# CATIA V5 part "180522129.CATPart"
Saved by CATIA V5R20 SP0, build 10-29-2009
Part number: 花瓶
Material "Fabric 4": density 200 kg/m3
Bounding box of the stored display mesh (mm): x -49.943 to 63.84, y -49.943 to 49.892, z 0 to 154
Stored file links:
  D:\工图\180522129.CATPart
  C:\Program Files\Dassault Systemes\B20\win_b64\startup\materials\Catalog.CATMaterial
  C:\Program Files\Dassault Systemes\B20\win_b64\startup\materials\canvas.png
  C:\Program Files\Dassault Systemes\B20\win_b64\startup\materials\solar_panel.jpg
  C:\Program Files\Dassault Systemes\B20\win_b64\startup\materials\summer_sky.jpg
  C:\Program Files\Dassault Systemes\B20\win_b64\startup\materials\green_env_512x512.jpg
  C:\Program Files\Dassault Systemes\B20\win_b64\startup\materials\losange_fabric.jpg
  C:\Program Files\Dassault Systemes\B20\win_b64\startup\materials\blue_fabric_01.jpg
  C:\Program Files\Dassault Systemes\B20\win_b64\startup\materials\office_carpet.jpg
  C:\Program Files\Dassault Systemes\B20\win_b64\startup\materials\wallpaper_01.jpg
  C:\Program Files\Dassault Systemes\B20\win_b64\startup\materials\grey_carpet.jpg
  C:\Program Files\Dassault Systemes\B20\win_b64\startup\materials\raw_polystyren.jpg
  C:\Program Files\Dassault Systemes\B20\win_b64\startup\materials\sunset.jpg
  C:\Program Files\Dassault Systemes\B20\win_b64\startup\materials\blue_carpet.jpg
  C:\Program Files\Dassault Systemes\B20\win_b64\startup\materials\wallpaper_03.jpg
  C:\Program Files\Dassault Systemes\B20\win_b64\startup\materials\wallpaper_02.jpg
  C:\Program Files\Dassault Systemes\B20\win_b64\startup\materials\DS_star.jpg
  C:\Program Files\Dassault Systemes\B20\win_b64\startup\materials\strip_wall.jpg
  C:\Program Files\Dassault Systemes\B20\win_b64\startup\materials\malachite.jpg
  C:\Program Files\Dassault Systemes\B20\win_b64\startup\materials\pink_marble.jpg
  C:\Program Files\Dassault Systemes\B20\win_b64\startup\materials\blue_env_512x512.jpg
  C:\Program Files\Dassault Systemes\B20\win_b64\startup\materials\red_env_512x512.jpg
  C:\Program Files\Dassault Systemes\B20\win_b64\startup\materials\kingwood.jpg
  C:\Program Files\Dassault Systemes\B20\win_b64\startup\materials\brushed_metal2.jpg
  C:\Program Files\Dassault Systemes\B20\win_b64\startup\materials\blue_fabric_02.jpg
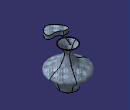
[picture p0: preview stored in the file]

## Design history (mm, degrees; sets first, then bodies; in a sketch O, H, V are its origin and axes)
Body1 (main body), material "Fabric 4"
  Plane1: type Offset, RefPlane xy-plane, Offset 20
  Plane2: type Offset, RefPlane Plane1, Offset 20
  Plane3: type Offset, RefPlane Plane2, Offset 20
  Plane4: type Offset, RefPlane Plane3, Offset 20
  Plane5: type Offset, RefPlane Plane4, Offset 20
  Sketch1 on Plane5, origin (0, 0, 100), H (1, 0, 0), V (0, 1, 0)
    circle A1 centre (0, 0) radius 22.3607
    radius A1 = 22.3607
  Sketch2 on Plane4, origin (0, 0, 80), H (1, 0, 0), V (0, 1, 0)
    circle A1 centre (0, 0) radius 10
    point P1 (10, 0)
    radius A1 = 10
    coincidence: A1 P1, P1 H
  Sketch3 on Plane3, origin (0, 0, 60), H (1, 0, 0), V (0, 1, 0)
    circle A1 centre (0, 0) radius 20
    radius A1 = 20
    radius A1 = 20 (reference)
  Sketch4 on Plane2, origin (0, 0, 40), H (1, 0, 0), V (0, 1, 0)
    circle A1 centre (0, 0) radius 50
    radius A1 = 50
  Sketch5 on Plane1, origin (0, 0, 20), H (1, 0, 0), V (0, 1, 0)
    circle A1 centre (0, 0) radius 30
    point P1 (30, 0)
    radius A1 = 30
    coincidence: A1 P1, P1 H
  Sketch6 on xy-plane, origin (0, 0, 0), H (1, 0, 0), V (0, 1, 0)
    circle A1 centre (0, 0) radius 22.3607
  Loft1: solid, Sections (Sketch1; Sketch2; Sketch3; Sketch4; Sketch5; Sketch6)
  Plane6: type Offset, RefPlane xy-plane, Offset 144
  Sketch7 on Plane6, origin (0, 0, 144), H (1, 0, 0), V (0, 1, 0)
    circle A1 centre (38.0963, 3.2822) radius 2.0095
  Sketch8 on zx-plane, origin (0, 0, 0), H (-1, 0, 0), V (0, 0, 1)
    spline S1 through (-38.919, 141.35) (-1.7437, 101.8697) (0, 36.6565)
    point P1 (0, 36.6565)
    coincidence: P1 V
  Rib1: profile Sketch7, centre curve Sketch8
  Sketch9 on Plane6, origin (0, 0, 144), H (1, 0, 0), V (0, 1, 0)
    spline S1 through (31.6091, 18.1068) (43.7665, 10.4521) (62.8709, 6.9727) (54.1871, -12.512) (26.3988, -9.0326) (15.6309, 16.3671) (31.6091, 18.1068)
    point P1 (31.6091, 18.1068)
    point P2 (31.6091, 18.1068)
    coincidence: P1 P2
  Pad1: profile Sketch9, direction (0, 0, 1), length 10
  Shell1: IntOffset 1, Face face of Loft1, ExtOffset 0, NonOffsetIn face of Rib1
  Shell2: IntOffset 1, ExtOffset 0
  Shell3: IntOffset 1, Face face of Loft1, ExtOffset 0
Body2
Current feature: Shell1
